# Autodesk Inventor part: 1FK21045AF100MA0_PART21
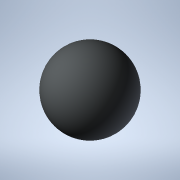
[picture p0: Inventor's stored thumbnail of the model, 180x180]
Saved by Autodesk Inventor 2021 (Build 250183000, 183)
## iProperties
Created: 2025-04
Part Number: 1FK21045AF100MA0_PART21
Material: Generic
Catalog Web Link: www.3dfindit.com
Description: -Servo synchronous motor
Document SubType Name: Modeling
Designer: psAdmin
Mass: 0.137258 g
Surface Area: 1.2868 cm^2
Volume: 0.137258 cm^3
Density: 1 g/cm^3
Appearance: PSOLRGB-212-217-219
Category: PARTsolutions
Title: 1FK21045AF100MA0_PART21
Author: Cadenas PARTsolutions
Comments: Servo synchronous motor
Sending System: PARTsolutions
Preprocessor: ST-DEVELOPER v19.3
PSOL_IDENT_0: {$CADENAS_DATA/23d-libs/siemens_ag/_cat_/52/6b/1fk21045af100ma0.prj},216 {VTYP=3D},{NB=1FK21045AF100
PSOL_IDENT_1: MA0_PART21},{LINA=1FK21045AF100MA0_PART21},{NN=1FK21045AF100MA0_PART21},{NOPRJ=TRUE},{DATE=19.08.202
PSOL_IDENT_2: 5 14:00:38},{GEOMDATE=30.07.2025 02:01:45},{VERSION=},{LINEID=10},{WBVAR=},{WBNUMERIC=}  {NB=1FK2104
PSOL_IDENT_3: 5AF100MA0_PART21},{LINA=1FK21045AF100MA0_PART21},{KT=DUMMY},{PREVIEW=../../../_pool_/cb/72/p_d211_xx
PSOL_IDENT_4: _00434j.png},{DESCSHORT=SIMOTICS S-1FK2 HD, SINAMICS S210 3AC 400V-480V, 2.4 Nm, 3000 rpm},{DESCLONG=
PSOL_IDENT_5: SIMOTICS S-1FK2 HD servo motor M0=2.4 Nm; PN = 0.75 kW at nN=3000 rpm (380-480 V); PN = 0.375 kW at
PSOL_IDENT_6: nN=1500 rpm (200-240 V); with holding brake; degree of protection IP64; cylindrical shaft D19x40mm;
PSOL_IDENT_7: absolute encoder 22-bit + 12-bit multiturn (encoder AM22DQC); with OCC interface; plug size M17, rot
PSOL_IDENT_8: atable; SIMOTICS S-1FK2 servomotorfor a wide range of uses in industrial environments. SIMOTICS S‑1F
PSOL_IDENT_9: K2 servomotors are compact synchronous motors with a high dynamic performance that set themselves ap
PSOL_IDENT_10: art as a result of their high power density, degree of protection and overload capability. The motor
PSOL_IDENT_11: s are available in two variants: as High Dynamic variant (highest dynamic performance as a result of
PSOL_IDENT_12: the low intrinsic moment of inertia for applications demanding a high dynamic performance with low
PSOL_IDENT_13: moved masses) - and as Compact variant (precise and stable closed-loop control for medium up to larg
PSOL_IDENT_14: e moved masses as a result of a medium intrinsic moment of inertia). SIMOTICSS‑1FK2 servomotors full
PSOL_IDENT_15: y exploit their strengths in a system with the SINAMICSS210 frequency converter and simple connectio
PSOL_IDENT_16: n using the one cable connection (OCC). Advantages include the short control and positioning times,
PSOL_IDENT_17: fast and precise correction of disturbing quantities as well as stable control with a high dynamic p
PSOL_IDENT_18: erformance. The servo motors can be configured to address a wide range of requirements. For example
PSOL_IDENT_19: with and without holding brake, IP64 or IP65 degree of protection, singleturn or multiturn absolute
PSOL_IDENT_20: encoders - to name just a few. Further, the servomotors are available in different shaft heights ext
PSOL_IDENT_21: ending from 20 to 100. A shaft sealing ring is available to achieve an IP65 degree of protection and
PSOL_IDENT_22: for subsequent mounting at the motor or as spare part. SIMOTICS - the optimum motor for each and ev
PSOL_IDENT_23: ery motion control application.},{INTNO=804766906411},{SUPPLIERALTNO=1FK2104-5AF10-0MA0},{MANUID=1FK
PSOL_IDENT_24: 21045AF100MA0},{MANUNAME=Siemens},{MANUTYPEDESC=Synchronous motor 1FK2-HD 2.4 NM},{AAU732=SIMOTICS},
PSOL_IDENT_25: {AAO057=S-1FK2},{AAU734=SIMOTICS S-1FK2 HD servo motor M0=2.4 Nm; PN = 0.75 kW at nN=3000 rpm (380-4
PSOL_IDENT_26: 80 V); PN = 0.375 kW at nN=1500 rpm (200-240 V); with holding brake; degree of protection IP64; cyli
PSOL_IDENT_27: ndrical shaft D19x40mm; absolute encoder 22-bit + 12-bit multiturn (encoder AM22DQC); with OCC inter
PSOL_IDENT_28: face; plug size M17, rotatable;},{AAW338=Synchronous motor 1FK2-HD 2.4 NM},{AAO742=SIMOTICS},{AAO663=
PSOL_IDENT_29: 4042948693070},{NOCUPEROU=1},{PRICEQUANTITY=1},{QUANTITYMIN=1},{QUANTITYINT=1},{CTN=85015100},{COO=D
PSOL_IDENT_30: E},{AAO676=1FK2104-5AF10-0MA0},{AAO677=Siemens AG},{ORDERUNIT=C62},{CONTENTUNIT=C62}
NB: 1FK21045AF100MA0_PART21
NT: Servo synchronous motor
NBSYN: $MANUID._PART21
LINA: 1FK21045AF100MA0_PART21
CATALOG: SIEMENS
PREVIEW: ../../../_pool_/cb/72/p_d211_xx_00434j.png
DESCSHORT: SIMOTICS S-1FK2 HD, SINAMICS S210 3AC 400V-480V, 2.4 Nm, 3000 rpm
DESCLONG: SIMOTICS S-1FK2 HD servo motor M0=2.4 Nm; PN = 0.75 kW at nN=3000 rpm (380-480 V); PN = 0.375 kW at nN=1500 rpm (200-240 V); with holding brake; degree of prote
INTNO: 804766906411
SUPPLIERALTNO: 1FK2104-5AF10-0MA0
MANUID: 1FK21045AF100MA0
MANUNAME: Siemens
MANUTYPEDESC: Synchronous motor 1FK2-HD 2.4 NM
AAU732: SIMOTICS
AAO057: S-1FK2
AAU734: SIMOTICS S-1FK2 HD servo motor M0=2.4 Nm; PN = 0.75 kW at nN=3000 rpm (380-480 V); PN = 0.375 kW at nN=1500 rpm (200-240 V); with holding brake; degree of prote
AAW338: Synchronous motor 1FK2-HD 2.4 NM
AAO742: SIMOTICS
AAO663: 4042948693070.0
NOCUPEROU: 1
PRICEQUANTITY: 1
QUANTITYMIN: 1
QUANTITYINT: 1
CTN: 85015100
COO: DE
ARTICLENO: 1FK21045AF100MA0_PART21
BOMINFO: 1FK21045AF100MA0_PART21
CREATOR: CADENAS GmbH
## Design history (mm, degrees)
feature "2025_04_17_15_34_52_0317"
body "Solid1"
